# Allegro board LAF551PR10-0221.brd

Outline 338.42 x 187.55 mm; copper layers: TOP, GND1, IN1, GND2, IN2, GND3, IN3, IN4, GND4, IN5, GND5, IN6, GND6, BOTTOM. Coordinates in mm from the lower left corner of the outline.

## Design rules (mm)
net group CHR_USB20_1: nets CHR_USB20_N1 CHR_USB20_P1
net group CHR_USB20_1_R: nets CHR_USB20_N1_R CHR_USB20_P1_R
net group CSO_1: nets CSON_1 CSOP_1
net group CSS_2: nets CSSN_2 CSSP_2
net group CSS_B+: nets CSSN_B+ CSSP_B+
net group CSSUM: nets CSNSUM CSPSUM
net group DDR-ALERT: nets DDR_A_ALERT# DDR_B_ALERT#
net group DIFFPAIR70: nets CSSN_1 CSSP_1
net group DIFFPAIR85: nets TP_CLK TP_DATA
net group DIFFPAIR176: nets VGA_SMB_CK2 VGA_SMB_DA2
net group DIFFPAIR180: nets TBTA_LSRX TBTA_LSTX
net group DIFFPAIR181: nets XTALIN XTALOUT
net group DIFFPAIR194: nets RTD3_CIO_PWR_EN RTD3_USB_PWR_EN
net group DIFFPAIR195: nets I2C_0_SCL_R I2C_0_SDA_R
net group DIFFPAIR196: nets I2C_0_SCL I2C_0_SDA
net group DIFFPAIR197: nets UART_2_PRXD_DTXD UART_2_PTXD_DRXD
net group DIFFPAIR199: nets USART_RX USART_TX
net group DIFFPAIR200: nets TP_CLK_R TP_DATA_R
net group DIFFPAIR201: nets TBT_A_SBU1 TBT_A_SBU2
net group I2C0__EC: nets I2C0_SCL_EC I2C0_SDA_EC
net group I2CC_: nets I2CC_SCL I2CC_SDA
net group I2CC__R: nets I2CC_SCL_R I2CC_SDA_R
net group NVVDD_ISUM1: nets NVVDD_ISUMN1 NVVDD_ISUMP1
net group NVVDD_ISUM2: nets NVVDD_ISUMN2 NVVDD_ISUMP2
net group NVVDD_ISUM3: nets NVVDD_ISUMN3 NVVDD_ISUMP3
net group NVVDD_ISUM4: nets NVVDD_ISUMN4 NVVDD_ISUMP4
net group PCIE_RCOMP: nets PCIE_RCOMPN PCIE_RCOMPP
net group RJ45_MDI0: nets RJ45_MDIN0 RJ45_MDIP0
net group RJ45_MDI1: nets RJ45_MDIN1 RJ45_MDIP1
net group RJ45_MDI2: nets RJ45_MDIN2 RJ45_MDIP2
net group RJ45_MDI3: nets RJ45_MDIN3 RJ45_MDIP3
net group SATA_PRX_C_DTX_0: nets SATA_PRX_C_DTX_N0 SATA_PRX_C_DTX_P0
net group SATA_PRX_DTX_0: nets SATA_PRX_DTX_N0 SATA_PRX_DTX_P0
net group SATA_PTX_C_DRX_0: nets SATA_PTX_C_DRX_N0 SATA_PTX_C_DRX_P0
net group SATA_PTX_DRX_0: nets SATA_PTX_DRX_N0 SATA_PTX_DRX_P0
net group SPK_L_CONN: nets SPK_L+_CONN SPK_L-_CONN
net group SPK_R_CONN: nets SPK_R+_CONN SPK_R-_CONN
net group VIN1: nets VIN1N VIN1P
net group VIN2: nets VIN2N VIN2P
net group VIN3: nets VIN3N VIN3P
net group 12: nets DGPU_PEX_RST#
net group 15: nets TBT_EE_CLK
net group 20: nets PCH_RTCRST#
net group ASYNCHRONOUS: nets CALDERA_RST# CDRA_RST# CFG0 CFG1 CFG2 CFG3 CFG4 CFG5 CFG6 CFG7 CFG8 CFG9 CFG10 CFG11 CFG12 CFG13 CFG14 CFG15 CFG16 CFG17 CFG18 CFG19 CFG_RCOMP CPU_TRIGGER DDR_DRAMRST# DGPU_HOLD_RST# DGPU_PEX_RST#_R DGPU_PWROK EDP_RCOMP GPU_PEX_RST_HOLD# H_CPUPWRGD H_DRAMRST# H_PECI H_PM_DOWN H_PM_SYNC_R H_PROCHOT# H_THERMTRIP# H_THERMTRIP#_R H_VCCST_PWRGD IMVP_VR_ON PCH_DPWROK PCH_JTAG_TCK PCH_PECI PCH_PLTRST# PCH_PWR_EN PCH_PWROK PCH_TRIGGER PECI_KB9012 PEG_RCOMP PLTRST_CPU# SLP_S3 SLP_S5 SUSACK# SUSP# SYS_PEX_RST_MON# SYS_PWROK SYS_RESET# SYSON TBT_RST#_R USB_OC0# USB_OC2# VCCIO_PGOOD VR_SVID_ALERT# VR_SVID_CLK VR_SVID_DATA XDP_PRDY# XDP_PREQ#
net group CODEC: nets HP2_D_L_C HP2_D_L_R HP2_D_R_C HP2_D_R_R HPOUT-L HPOUT-R
net group CRITICAL LOW SPEED: nets INTRUDER# PBTN_OUT# PCH_SRTCRST# PCIE_WAKE# WAKE#
net group CRYSTAL: nets PCH_RTCX1 PCH_RTCX2 TBT_XTAL_25_IN TBT_XTAL_25_OUT XTAL24_IN XTAL24_OUT XTLI XTLO
net group DDR-RCOMP: nets DDR_RCOMP0 DDR_RCOMP1 DDR_RCOMP2
net group DDRA-CMD: nets DDR_A_BA0 DDR_A_BA1 DDR_A_BG0 DDR_A_BG1 DDR_A_MA0 DDR_A_MA1 DDR_A_MA2 DDR_A_MA3 DDR_A_MA4 DDR_A_MA5 DDR_A_MA6 DDR_A_MA7 DDR_A_MA8 DDR_A_MA9 DDR_A_MA10 DDR_A_MA11 DDR_A_MA12 DDR_A_MA13 DDR_A_MA14_WE# DDR_A_MA15_CAS# DDR_A_MA16_RAS#
net group DDRA-CTL: nets DDR_A_ACT# DDR_A_CKE0 DDR_A_CKE1 DDR_A_CS#0 DDR_A_CS#1 DDR_A_ODT0 DDR_A_ODT1 DDR_A_PAR
net group DDRA-D0: nets DDR_A_D0 DDR_A_D1 DDR_A_D2 DDR_A_D3 DDR_A_D4 DDR_A_D5 DDR_A_D6 DDR_A_D7
net group DDRA-D1: nets DDR_A_D8 DDR_A_D9 DDR_A_D10 DDR_A_D11 DDR_A_D12 DDR_A_D13 DDR_A_D14 DDR_A_D15
net group DDRA-D2: nets DDR_A_D16 DDR_A_D17 DDR_A_D18 DDR_A_D19 DDR_A_D20 DDR_A_D21 DDR_A_D22 DDR_A_D23
net group DDRA-D3: nets DDR_A_D24 DDR_A_D25 DDR_A_D26 DDR_A_D27 DDR_A_D28 DDR_A_D29 DDR_A_D30 DDR_A_D31
net group DDRA-D4: nets DDR_A_D32 DDR_A_D33 DDR_A_D34 DDR_A_D35 DDR_A_D36 DDR_A_D37 DDR_A_D38 DDR_A_D39
net group DDRA-D5: nets DDR_A_D40 DDR_A_D41 DDR_A_D42 DDR_A_D43 DDR_A_D44 DDR_A_D45 DDR_A_D46 DDR_A_D47
net group DDRA-D6: nets DDR_A_D48 DDR_A_D49 DDR_A_D50 DDR_A_D51 DDR_A_D52 DDR_A_D53 DDR_A_D54 DDR_A_D55
net group DDRA-D7: nets DDR_A_D56 DDR_A_D57 DDR_A_D58 DDR_A_D59 DDR_A_D60 DDR_A_D61 DDR_A_D62 DDR_A_D63
net group DDRA-DQS: nets DDR_A_DQS0 DDR_A_DQS1 DDR_A_DQS2 DDR_A_DQS3 DDR_A_DQS4 DDR_A_DQS5 DDR_A_DQS6 DDR_A_DQS7 DDR_A_DQS#0 DDR_A_DQS#1 DDR_A_DQS#2 DDR_A_DQS#3 DDR_A_DQS#4 DDR_A_DQS#5 DDR_A_DQS#6 DDR_A_DQS#7
net group DDRB-CMD: nets DDR_B_BA0 DDR_B_BA1 DDR_B_BG0 DDR_B_BG1 DDR_B_MA0 DDR_B_MA1 DDR_B_MA2 DDR_B_MA3 DDR_B_MA4 DDR_B_MA5 DDR_B_MA6 DDR_B_MA7 DDR_B_MA8 DDR_B_MA9 DDR_B_MA10 DDR_B_MA11 DDR_B_MA12 DDR_B_MA13 DDR_B_MA14_WE# DDR_B_MA15_CAS# DDR_B_MA16_RAS#
net group DDRB-CTL: nets DDR_B_ACT# DDR_B_CKE0 DDR_B_CKE1 DDR_B_CS#0 DDR_B_CS#1 DDR_B_ODT0 DDR_B_ODT1 DDR_B_PAR
net group DDRB-D0: nets DDR_B_D0 DDR_B_D1 DDR_B_D2 DDR_B_D3 DDR_B_D4 DDR_B_D5 DDR_B_D6 DDR_B_D7
net group DDRB-D1: nets DDR_B_D8 DDR_B_D9 DDR_B_D10 DDR_B_D11 DDR_B_D12 DDR_B_D13 DDR_B_D14 DDR_B_D15
net group DDRB-D2: nets DDR_B_D16 DDR_B_D17 DDR_B_D18 DDR_B_D19 DDR_B_D20 DDR_B_D21 DDR_B_D22 DDR_B_D23
net group DDRB-D3: nets DDR_B_D24 DDR_B_D25 DDR_B_D26 DDR_B_D27 DDR_B_D28 DDR_B_D29 DDR_B_D30 DDR_B_D31
net group DDRB-D4: nets DDR_B_D32 DDR_B_D33 DDR_B_D34 DDR_B_D35 DDR_B_D36 DDR_B_D37 DDR_B_D38 DDR_B_D39
net group DDRB-D5: nets DDR_B_D40 DDR_B_D41 DDR_B_D42 DDR_B_D43 DDR_B_D44 DDR_B_D45 DDR_B_D46 DDR_B_D47
net group DDRB-D6: nets DDR_B_D48 DDR_B_D49 DDR_B_D50 DDR_B_D51 DDR_B_D52 DDR_B_D53 DDR_B_D54 DDR_B_D55
net group DDRB-D7: nets DDR_B_D56 DDR_B_D57 DDR_B_D58 DDR_B_D59 DDR_B_D60 DDR_B_D61 DDR_B_D62 DDR_B_D63
net group DDRB-DQS: nets DDR_B_DQS0 DDR_B_DQS1 DDR_B_DQS2 DDR_B_DQS3 DDR_B_DQS4 DDR_B_DQS5 DDR_B_DQS6 DDR_B_DQS7 DDR_B_DQS#0 DDR_B_DQS#1 DDR_B_DQS#2 DDR_B_DQS#3 DDR_B_DQS#4 DDR_B_DQS#5 DDR_B_DQS#6 DDR_B_DQS#7
net group DDRCLK: nets DDR_A_CLK0 DDR_A_CLK1 DDR_A_CLK#0 DDR_A_CLK#1 DDR_B_CLK0 DDR_B_CLK1 DDR_B_CLK#0 DDR_B_CLK#1
net group DIFFPAIR148: nets REMOTE3-
net group DMI: nets DMI_CRX_PTX_N0 DMI_CRX_PTX_N1 DMI_CRX_PTX_N2 DMI_CRX_PTX_N3 DMI_CRX_PTX_P0 DMI_CRX_PTX_P1 DMI_CRX_PTX_P2 DMI_CRX_PTX_P3 DMI_CTX_PRX_N0 DMI_CTX_PRX_N1 DMI_CTX_PRX_N2 DMI_CTX_PRX_N3 DMI_CTX_PRX_P0 DMI_CTX_PRX_P1 DMI_CTX_PRX_P2 DMI_CTX_PRX_P3 DMIC_CLK1_R DMIC_DATA1_R
net group DP: nets CPU_DDC1CLK CPU_DDC1CLK_R CPU_DDC1DATA CPU_DDC1DATA_R CPU_DDC2CLK CPU_DDC2CLK_R CPU_DDC2DATA CPU_DDC2DATA_R CPU_DP1_AUXN CPU_DP1_AUXN_C CPU_DP1_AUXP CPU_DP1_AUXP_C CPU_DP1_N0 CPU_DP1_N0_C CPU_DP1_N1 CPU_DP1_N1_C CPU_DP1_N2 CPU_DP1_N2_C CPU_DP1_N3 CPU_DP1_N3_C CPU_DP1_P0 CPU_DP1_P0_C CPU_DP1_P1 CPU_DP1_P1_C CPU_DP1_P2 CPU_DP1_P2_C CPU_DP1_P3 CPU_DP1_P3_C CPU_DP2_AUXN CPU_DP2_AUXN_C CPU_DP2_AUXP CPU_DP2_AUXP_C CPU_DP2_N0 CPU_DP2_N0_C CPU_DP2_N1 CPU_DP2_N1_C CPU_DP2_N2 CPU_DP2_N2_C CPU_DP2_N3 CPU_DP2_N3_C CPU_DP2_P0 CPU_DP2_P0_C CPU_DP2_P1 CPU_DP2_P1_C CPU_DP2_P2 CPU_DP2_P2_C CPU_DP2_P3 CPU_DP2_P3_C GPU_DP_AUXN GPU_DP_AUXN_C GPU_DP_AUXN_R GPU_DP_AUXP GPU_DP_AUXP_C GPU_DP_AUXP_R GPU_DP_N0 GPU_DP_N0_C GPU_DP_N1 GPU_DP_N1_C GPU_DP_N2 GPU_DP_N2_C GPU_DP_N3 GPU_DP_N3_C GPU_DP_P0 GPU_DP_P0_C GPU_DP_P1 GPU_DP_P1_C GPU_DP_P2 GPU_DP_P2_C GPU_DP_P3 GPU_DP_P3_C
net group EDP-MUX: nets EDP_AUXN EDP_AUXN_C EDP_AUXP EDP_AUXP_C EDP_TXN0 EDP_TXN0_C EDP_TXN1 EDP_TXN1_C EDP_TXN2 EDP_TXN2_C EDP_TXN3 EDP_TXN3_C EDP_TXP0 EDP_TXP0_C EDP_TXP1 EDP_TXP1_C EDP_TXP2 EDP_TXP2_C EDP_TXP3 EDP_TXP3_C
net group EMC: nets BOOT_1.2V BST_1.2V BST_3V BST_5V CPU_XDP_TRST# MIC_CLK MIC_DATA RJ45_CT0 RJ45_CT1 RJ45_CT2 RJ45_CT3 TBT_TCK
net group FB_A_WCK01: nets FB_A_WCK#01
net group FB_A_WCK23: nets FB_A_WCK#23
net group FB_A_WCK45: nets FB_A_WCK#45
net group FB_A_WCK67: nets FB_A_WCK#67
net group FBA-CLK: nets FB_A_CLK0 FB_A_CLK1 FB_A_CLK#0 FB_A_CLK#1
net group FBA-CMD: nets FB_A_CMD0 FB_A_CMD1 FB_A_CMD2 FB_A_CMD3 FB_A_CMD4 FB_A_CMD5 FB_A_CMD6 FB_A_CMD7 FB_A_CMD8 FB_A_CMD9 FB_A_CMD10 FB_A_CMD11 FB_A_CMD12 FB_A_CMD13 FB_A_CMD14 FB_A_CMD15 FB_A_CMD16 FB_A_CMD17 FB_A_CMD18 FB_A_CMD19 FB_A_CMD20 FB_A_CMD21 FB_A_CMD22 FB_A_CMD23 FB_A_CMD24 FB_A_CMD25 FB_A_CMD26 FB_A_CMD27 FB_A_CMD28 FB_A_CMD29 FB_A_CMD30 FB_A_CMD31
net group FBA-D0: nets FB_A_D0 FB_A_D1 FB_A_D2 FB_A_D3 FB_A_D4 FB_A_D5 FB_A_D6 FB_A_D7
net group FBA-D1: nets FB_A_D8 FB_A_D9 FB_A_D10 FB_A_D11 FB_A_D12 FB_A_D13 FB_A_D14 FB_A_D15
net group FBA-D2: nets FB_A_D16 FB_A_D17 FB_A_D18 FB_A_D19 FB_A_D20 FB_A_D21 FB_A_D22 FB_A_D23
net group FBA-D3: nets FB_A_D24 FB_A_D25 FB_A_D26 FB_A_D27 FB_A_D28 FB_A_D29 FB_A_D30 FB_A_D31
net group FBA-D4: nets FB_A_D32 FB_A_D33 FB_A_D34 FB_A_D35 FB_A_D36 FB_A_D37 FB_A_D38 FB_A_D39
net group FBA-D5: nets FB_A_D40 FB_A_D41 FB_A_D42 FB_A_D43 FB_A_D44 FB_A_D45 FB_A_D46 FB_A_D47
net group FBA-D6: nets FB_A_D48 FB_A_D49 FB_A_D50 FB_A_D51 FB_A_D52 FB_A_D53 FB_A_D54 FB_A_D55
net group FBA-D7: nets FB_A_D56 FB_A_D57 FB_A_D58 FB_A_D59 FB_A_D60 FB_A_D61 FB_A_D62 FB_A_D63
net group FBA-DBI: nets FB_A_DBI0 FB_A_DBI1 FB_A_DBI2 FB_A_DBI3 FB_A_DBI4 FB_A_DBI5 FB_A_DBI6 FB_A_DBI7
net group FBA-EDC: nets FB_A_EDC0 FB_A_EDC1 FB_A_EDC2 FB_A_EDC3 FB_A_EDC4 FB_A_EDC5 FB_A_EDC6 FB_A_EDC7
net group FBA-WCK: nets FB_A_WCK01 FB_A_WCK23 FB_A_WCK45 FB_A_WCK67
net group FBB-CLK: nets FB_B_CLK0 FB_B_CLK1 FB_B_CLK#0 FB_B_CLK#1
net group FBB-CMD: nets FB_B_CMD0 FB_B_CMD1 FB_B_CMD2 FB_B_CMD3 FB_B_CMD4 FB_B_CMD5 FB_B_CMD6 FB_B_CMD7 FB_B_CMD8 FB_B_CMD9 FB_B_CMD10 FB_B_CMD11 FB_B_CMD12 FB_B_CMD13 FB_B_CMD14 FB_B_CMD15 FB_B_CMD16 FB_B_CMD17 FB_B_CMD18 FB_B_CMD19 FB_B_CMD20 FB_B_CMD21 FB_B_CMD22 FB_B_CMD23 FB_B_CMD24 FB_B_CMD25 FB_B_CMD26 FB_B_CMD27 FB_B_CMD28 FB_B_CMD29 FB_B_CMD30 FB_B_CMD31
net group FBB-D0: nets FB_B_D0 FB_B_D1 FB_B_D2 FB_B_D3 FB_B_D4 FB_B_D5 FB_B_D6 FB_B_D7
net group FBB-D1: nets FB_B_D8 FB_B_D9 FB_B_D10 FB_B_D11 FB_B_D12 FB_B_D13 FB_B_D14 FB_B_D15
net group FBB-D2: nets FB_B_D16 FB_B_D17 FB_B_D18 FB_B_D19 FB_B_D20 FB_B_D21 FB_B_D22 FB_B_D23
net group FBB-D3: nets FB_B_D24 FB_B_D25 FB_B_D26 FB_B_D27 FB_B_D28 FB_B_D29 FB_B_D30 FB_B_D31
net group FBB-D4: nets FB_B_D32 FB_B_D33 FB_B_D34 FB_B_D35 FB_B_D36 FB_B_D37 FB_B_D38 FB_B_D39
net group FBB-D5: nets FB_B_D40 FB_B_D41 FB_B_D42 FB_B_D43 FB_B_D44 FB_B_D45 FB_B_D46 FB_B_D47
net group FBB-D6: nets FB_B_D48 FB_B_D49 FB_B_D50 FB_B_D51 FB_B_D52 FB_B_D53 FB_B_D54 FB_B_D55
net group FBB-D7: nets FB_B_D56 FB_B_D57 FB_B_D58 FB_B_D59 FB_B_D60 FB_B_D61 FB_B_D62 FB_B_D63
net group FBB-DBI: nets FB_B_DBI0 FB_B_DBI1 FB_B_DBI2 FB_B_DBI3 FB_B_DBI4 FB_B_DBI5 FB_B_DBI6 FB_B_DBI7
net group FBB-EDC: nets FB_B_EDC0 FB_B_EDC1 FB_B_EDC2 FB_B_EDC3 FB_B_EDC4 FB_B_EDC5 FB_B_EDC6 FB_B_EDC7
net group FBB-WCK: nets FB_B_WCK01 FB_B_WCK23 FB_B_WCK45 FB_B_WCK67 FB_B_WCK#01 FB_B_WCK#23 FB_B_WCK#45 FB_B_WCK#67
net group FBC-CLK: nets FB_C_CLK0 FB_C_CLK1 FB_C_CLK#0 FB_C_CLK#1
net group FBC-CMD: nets FB_C_CMD0 FB_C_CMD1 FB_C_CMD2 FB_C_CMD3 FB_C_CMD4 FB_C_CMD5 FB_C_CMD6 FB_C_CMD7 FB_C_CMD8 FB_C_CMD9 FB_C_CMD10 FB_C_CMD11 FB_C_CMD12 FB_C_CMD13 FB_C_CMD14 FB_C_CMD15 FB_C_CMD16 FB_C_CMD17 FB_C_CMD18 FB_C_CMD19 FB_C_CMD20 FB_C_CMD21 FB_C_CMD22 FB_C_CMD23 FB_C_CMD24 FB_C_CMD25 FB_C_CMD26 FB_C_CMD27 FB_C_CMD28 FB_C_CMD29 FB_C_CMD30 FB_C_CMD31
net group FBC-D0: nets FB_C_D0 FB_C_D1 FB_C_D2 FB_C_D3 FB_C_D4 FB_C_D5 FB_C_D6 FB_C_D7
net group FBC-D1: nets FB_C_D8 FB_C_D9 FB_C_D10 FB_C_D11 FB_C_D12 FB_C_D13 FB_C_D14 FB_C_D15
net group FBC-D2: nets FB_C_D16 FB_C_D17 FB_C_D18 FB_C_D19 FB_C_D20 FB_C_D21 FB_C_D22 FB_C_D23
net group FBC-D3: nets FB_C_D24 FB_C_D25 FB_C_D26 FB_C_D27 FB_C_D28 FB_C_D29 FB_C_D30 FB_C_D31
net group FBC-D4: nets FB_C_D32 FB_C_D33 FB_C_D34 FB_C_D35 FB_C_D36 FB_C_D37 FB_C_D38 FB_C_D39
net group FBC-D5: nets FB_C_D40 FB_C_D41 FB_C_D42 FB_C_D43 FB_C_D44 FB_C_D45 FB_C_D46 FB_C_D47
net group FBC-D6: nets FB_C_D48 FB_C_D49 FB_C_D50 FB_C_D51 FB_C_D52 FB_C_D53 FB_C_D54 FB_C_D55
net group FBC-D7: nets FB_C_D56 FB_C_D57 FB_C_D58 FB_C_D59 FB_C_D60 FB_C_D61 FB_C_D62 FB_C_D63
net group FBC-DBI: nets FB_C_DBI0 FB_C_DBI1 FB_C_DBI2 FB_C_DBI3 FB_C_DBI4 FB_C_DBI5 FB_C_DBI6 FB_C_DBI7
net group FBC-EDC: nets FB_C_EDC0 FB_C_EDC1 FB_C_EDC2 FB_C_EDC3 FB_C_EDC4 FB_C_EDC5 FB_C_EDC6 FB_C_EDC7
net group FBC-WCK: nets FB_C_WCK01 FB_C_WCK23 FB_C_WCK45 FB_C_WCK67 FB_C_WCK#01 FB_C_WCK#23 FB_C_WCK#45 FB_C_WCK#67
net group FBD-CLK: nets FB_D_CLK0 FB_D_CLK1 FB_D_CLK#0 FB_D_CLK#1
net group FBD-CMD: nets FB_D_CMD0 FB_D_CMD1 FB_D_CMD2 FB_D_CMD3 FB_D_CMD4 FB_D_CMD5 FB_D_CMD6 FB_D_CMD7 FB_D_CMD8 FB_D_CMD9 FB_D_CMD10 FB_D_CMD11 FB_D_CMD12 FB_D_CMD13 FB_D_CMD14 FB_D_CMD15 FB_D_CMD16 FB_D_CMD17 FB_D_CMD18 FB_D_CMD19 FB_D_CMD20 FB_D_CMD21 FB_D_CMD22 FB_D_CMD23 FB_D_CMD24 FB_D_CMD25 FB_D_CMD26 FB_D_CMD27 FB_D_CMD28 FB_D_CMD29 FB_D_CMD30 FB_D_CMD31
net group FBD-D0: nets FB_D_D0 FB_D_D1 FB_D_D2 FB_D_D3 FB_D_D4 FB_D_D5 FB_D_D6 FB_D_D7
net group FBD-D1: nets FB_D_D8 FB_D_D9 FB_D_D10 FB_D_D11 FB_D_D12 FB_D_D13 FB_D_D14 FB_D_D15
net group FBD-D2: nets FB_D_D16 FB_D_D17 FB_D_D18 FB_D_D19 FB_D_D20 FB_D_D21 FB_D_D22 FB_D_D23
net group FBD-D3: nets FB_D_D24 FB_D_D25 FB_D_D26 FB_D_D27 FB_D_D28 FB_D_D29 FB_D_D30 FB_D_D31
net group FBD-D4: nets FB_D_D32 FB_D_D33 FB_D_D34 FB_D_D35 FB_D_D36 FB_D_D37 FB_D_D38 FB_D_D39
net group FBD-D5: nets FB_D_D40 FB_D_D41 FB_D_D42 FB_D_D43 FB_D_D44 FB_D_D45 FB_D_D46 FB_D_D47
net group FBD-D6: nets FB_D_D48 FB_D_D49 FB_D_D50 FB_D_D51 FB_D_D52 FB_D_D53 FB_D_D54 FB_D_D55
net group FBD-D7: nets FB_D_D56 FB_D_D57 FB_D_D58 FB_D_D59 FB_D_D60 FB_D_D61 FB_D_D62 FB_D_D63
net group FBD-DBI: nets FB_D_DBI0 FB_D_DBI1 FB_D_DBI2 FB_D_DBI3 FB_D_DBI4 FB_D_DBI5 FB_D_DBI6 FB_D_DBI7
net group FBD-EDC: nets FB_D_EDC0 FB_D_EDC1 FB_D_EDC2 FB_D_EDC3 FB_D_EDC4 FB_D_EDC5 FB_D_EDC6 FB_D_EDC7
net group FBD-WCK: nets FB_D_WCK01 FB_D_WCK23 FB_D_WCK45 FB_D_WCK67 FB_D_WCK#01 FB_D_WCK#23 FB_D_WCK#45 FB_D_WCK#67
net group HDA: nets HDA_BIT_CLK HDA_BIT_CLK_R HDA_RST# HDA_RST#_R HDA_SDIN HDA_SDIN_R HDA_SDOUT HDA_SDOUT_R HDA_SPKR HDA_SYNC HDA_SYNC_R ME_EN
net group HDMI: nets GPU_HDMI_CLKN GPU_HDMI_CLKP GPU_HDMI_TX_N0 GPU_HDMI_TX_N1 GPU_HDMI_TX_N2 GPU_HDMI_TX_P0 GPU_HDMI_TX_P1 GPU_HDMI_TX_P2 HDMI_C_CLKN HDMI_C_CLKP HDMI_C_TX_N0 HDMI_C_TX_N1 HDMI_C_TX_N2 HDMI_C_TX_P0 HDMI_C_TX_P1 HDMI_C_TX_P2 HDMI_CLKN HDMI_CLKP HDMI_L_CLKN HDMI_L_CLKP HDMI_L_TX_N0 HDMI_L_TX_N1 HDMI_L_TX_N2 HDMI_L_TX_P0 HDMI_L_TX_P1 HDMI_L_TX_P2 HDMI_TX_N0 HDMI_TX_N1 HDMI_TX_N2 HDMI_TX_P0 HDMI_TX_P1 HDMI_TX_P2
net group I2C: nets CDRA_CLK CDRA_DAT I2C_CLK I2C_DAT I2C_INT TBT_I2C_SCL TBT_I2C_SDA TBTA_I2C_INT TBTA_I2C_SCL1_R TBTA_I2C_SDA1_R TBTB_I2C_INT
net group LAN: nets LAN_MDIN0 LAN_MDIN1 LAN_MDIN2 LAN_MDIN3 LAN_MDIP0 LAN_MDIP1 LAN_MDIP2 LAN_MDIP3
net group LPC: nets LPC_AD0 LPC_AD1 LPC_AD2 LPC_AD3 LPC_FRAME#
net group MDP: nets DISP_CLK_AUXP_CONN
net group PCIE: nets PCIE_PRX_C_DTX_N15 PCIE_PRX_C_DTX_P15 PCIE_PRX_DTX_N9 PCIE_PRX_DTX_N10 PCIE_PRX_DTX_N11 PCIE_PRX_DTX_N12 PCIE_PRX_DTX_N15 PCIE_PRX_DTX_N16 PCIE_PRX_DTX_N17 PCIE_PRX_DTX_N18 PCIE_PRX_DTX_N19 PCIE_PRX_DTX_N20 PCIE_PRX_DTX_N21 PCIE_PRX_DTX_N22 PCIE_PRX_DTX_N23 PCIE_PRX_DTX_N24 PCIE_PRX_DTX_P9 PCIE_PRX_DTX_P10 PCIE_PRX_DTX_P11 PCIE_PRX_DTX_P12 PCIE_PRX_DTX_P15 PCIE_PRX_DTX_P16 PCIE_PRX_DTX_P17 PCIE_PRX_DTX_P18 PCIE_PRX_DTX_P19 PCIE_PRX_DTX_P20 PCIE_PRX_DTX_P21 PCIE_PRX_DTX_P22 PCIE_PRX_DTX_P23 PCIE_PRX_DTX_P24 PCIE_PTX_C_DRX_N9 PCIE_PTX_C_DRX_N10 PCIE_PTX_C_DRX_N11 PCIE_PTX_C_DRX_N12 PCIE_PTX_C_DRX_N15 PCIE_PTX_C_DRX_N16 PCIE_PTX_C_DRX_N17 PCIE_PTX_C_DRX_N18 PCIE_PTX_C_DRX_N19 PCIE_PTX_C_DRX_N20 PCIE_PTX_C_DRX_N21 PCIE_PTX_C_DRX_N22 PCIE_PTX_C_DRX_N23 PCIE_PTX_C_DRX_N24 PCIE_PTX_C_DRX_P9 PCIE_PTX_C_DRX_P10 PCIE_PTX_C_DRX_P11 PCIE_PTX_C_DRX_P12 PCIE_PTX_C_DRX_P15 PCIE_PTX_C_DRX_P16 PCIE_PTX_C_DRX_P17 PCIE_PTX_C_DRX_P18 PCIE_PTX_C_DRX_P19 PCIE_PTX_C_DRX_P20 PCIE_PTX_C_DRX_P21 PCIE_PTX_C_DRX_P22 PCIE_PTX_C_DRX_P23 PCIE_PTX_C_DRX_P24 PCIE_PTX_DRX_N9 PCIE_PTX_DRX_N10 PCIE_PTX_DRX_N11 PCIE_PTX_DRX_N12 PCIE_PTX_DRX_N15 PCIE_PTX_DRX_N16 PCIE_PTX_DRX_N17 PCIE_PTX_DRX_N18 PCIE_PTX_DRX_N19 PCIE_PTX_DRX_N20 PCIE_PTX_DRX_N21 PCIE_PTX_DRX_N22 PCIE_PTX_DRX_N23 PCIE_PTX_DRX_N24 PCIE_PTX_DRX_P9 PCIE_PTX_DRX_P10 PCIE_PTX_DRX_P11 PCIE_PTX_DRX_P12 PCIE_PTX_DRX_P15 PCIE_PTX_DRX_P16 PCIE_PTX_DRX_P17 PCIE_PTX_DRX_P18 PCIE_PTX_DRX_P19 PCIE_PTX_DRX_P20 PCIE_PTX_DRX_P21 PCIE_PTX_DRX_P22 PCIE_PTX_DRX_P23 PCIE_PTX_DRX_P24
net group PEG: nets PEG_CRX_C_GTX_N0 PEG_CRX_C_GTX_N1 PEG_CRX_C_GTX_N2 PEG_CRX_C_GTX_N3 PEG_CRX_C_GTX_N4 PEG_CRX_C_GTX_N5 PEG_CRX_C_GTX_N6 PEG_CRX_C_GTX_N7 PEG_CRX_C_GTX_P0 PEG_CRX_C_GTX_P1 PEG_CRX_C_GTX_P2 PEG_CRX_C_GTX_P3 PEG_CRX_C_GTX_P4 PEG_CRX_C_GTX_P5 PEG_CRX_C_GTX_P6 PEG_CRX_C_GTX_P7 PEG_CRX_C_RD_GTX_N8 PEG_CRX_C_RD_GTX_N9 PEG_CRX_C_RD_GTX_N10 PEG_CRX_C_RD_GTX_N11 PEG_CRX_C_RD_GTX_P8 PEG_CRX_C_RD_GTX_P9 PEG_CRX_C_RD_GTX_P10 PEG_CRX_C_RD_GTX_P11 PEG_CRX_C_TTX_N12 PEG_CRX_C_TTX_N13 PEG_CRX_C_TTX_N14 PEG_CRX_C_TTX_N15 PEG_CRX_C_TTX_P12 PEG_CRX_C_TTX_P13 PEG_CRX_C_TTX_P14 PEG_CRX_C_TTX_P15 PEG_CRX_GTX_N0 PEG_CRX_GTX_N1 PEG_CRX_GTX_N2 PEG_CRX_GTX_N3 PEG_CRX_GTX_N4 PEG_CRX_GTX_N5 PEG_CRX_GTX_N6 PEG_CRX_GTX_N7 PEG_CRX_GTX_N8 PEG_CRX_GTX_N9 PEG_CRX_GTX_N10 PEG_CRX_GTX_N11 PEG_CRX_GTX_P0 PEG_CRX_GTX_P1 PEG_CRX_GTX_P2 PEG_CRX_GTX_P3 PEG_CRX_GTX_P4 PEG_CRX_GTX_P5 PEG_CRX_GTX_P6 PEG_CRX_GTX_P7 PEG_CRX_GTX_P8 PEG_CRX_GTX_P9 PEG_CRX_GTX_P10 PEG_CRX_GTX_P11 PEG_CRX_RD_GTX_N8 PEG_CRX_RD_GTX_N9 PEG_CRX_RD_GTX_N10 PEG_CRX_RD_GTX_N11 PEG_CRX_RD_GTX_P8 PEG_CRX_RD_GTX_P9 PEG_CRX_RD_GTX_P10 PEG_CRX_RD_GTX_P11 PEG_CRX_TTX_N12 PEG_CRX_TTX_N13 PEG_CRX_TTX_N14 PEG_CRX_TTX_N15 PEG_CRX_TTX_P12 PEG_CRX_TTX_P13 PEG_CRX_TTX_P14 PEG_CRX_TTX_P15 PEG_CTX_C_GRX_N0 PEG_CTX_C_GRX_N1 PEG_CTX_C_GRX_N2 PEG_CTX_C_GRX_N3 PEG_CTX_C_GRX_N4 PEG_CTX_C_GRX_N5 PEG_CTX_C_GRX_N6 PEG_CTX_C_GRX_N7 PEG_CTX_C_GRX_N8 PEG_CTX_C_GRX_N9 PEG_CTX_C_GRX_N10 PEG_CTX_C_GRX_N11 PEG_CTX_C_GRX_P0 PEG_CTX_C_GRX_P1 PEG_CTX_C_GRX_P2 PEG_CTX_C_GRX_P3 PEG_CTX_C_GRX_P4 PEG_CTX_C_GRX_P5 PEG_CTX_C_GRX_P6 PEG_CTX_C_GRX_P7 PEG_CTX_C_GRX_P8 PEG_CTX_C_GRX_P9 PEG_CTX_C_GRX_P10 PEG_CTX_C_GRX_P11 PEG_CTX_C_TRX_N12 PEG_CTX_C_TRX_N13 PEG_CTX_C_TRX_N14 PEG_CTX_C_TRX_N15 PEG_CTX_C_TRX_P12 PEG_CTX_C_TRX_P13 PEG_CTX_C_TRX_P14 PEG_CTX_C_TRX_P15 PEG_CTX_GRX_N0 PEG_CTX_GRX_N1 PEG_CTX_GRX_N2 PEG_CTX_GRX_N3 PEG_CTX_GRX_N4 PEG_CTX_GRX_N5 PEG_CTX_GRX_N6 PEG_CTX_GRX_N7 PEG_CTX_GRX_N8 PEG_CTX_GRX_N9 PEG_CTX_GRX_N10 PEG_CTX_GRX_N11 PEG_CTX_GRX_P0 PEG_CTX_GRX_P1 PEG_CTX_GRX_P2 PEG_CTX_GRX_P3 PEG_CTX_GRX_P4 PEG_CTX_GRX_P5 PEG_CTX_GRX_P6 PEG_CTX_GRX_P7 PEG_CTX_GRX_P8 PEG_CTX_GRX_P9 PEG_CTX_GRX_P10 PEG_CTX_GRX_P11 PEG_CTX_TRX_N12 PEG_CTX_TRX_N13 PEG_CTX_TRX_N14 PEG_CTX_TRX_N15 PEG_CTX_TRX_P12 PEG_CTX_TRX_P13 PEG_CTX_TRX_P14 PEG_CTX_TRX_P15
net group PLATFORM-CLK: nets CLK_PCI_LPC CLK_PCIE_DGPU#_C CLK_PCIE_DGPU_C CLK_PCIE_N1 CLK_PCIE_N2 CLK_PCIE_N3 CLK_PCIE_N4 CLK_PCIE_N5 CLK_PCIE_N7 CLK_PCIE_P1 CLK_PCIE_P2 CLK_PCIE_P3 CLK_PCIE_P4 CLK_PCIE_P5 CLK_PCIE_P7 CLK_PEG_N0 CLK_PEG_N6 CLK_PEG_P0 CLK_PEG_P6 CPU_24MHZ_N CPU_24MHZ_P PCH_CPU_BCLK_N PCH_CPU_BCLK_P PCH_CPU_PCIBCLK_N PCH_CPU_PCIBCLK_P PCH_XDP_CLK_N PCH_XDP_CLK_P
net group POWER: nets +0.6VS +0.6VSP +0.9V_CIO +0.9V_LVR_OUT +0.9V_SVR +0.9V_USB +1.2V_VCCPLL_OC +1.2VP +1.8VA_TBTA_LDO +1.8VD_TBTA_LDO +1V_MPHY +1V_PCH +1V_VCCDSW +1VALWP +1VALWP_B+ +2.5V_MEM +2.5V_MEMP +2.5VOUT +2.5VSP_ON +2.5VSP_VIN +3.3V_1.8V_DVDD +3.3V_1.8V_DVDD_IO +3.3V_ANA_PCIE +3.3V_ANA_USB2 +3.3V_FLASH +3.3V_LC +3.3V_TBT_SX +3.3V_TBT_SX_R +3V_PCH +3VALW_PD +3VALWP +3VLP +3VS_DP +3VS_TBT +3VS_TOUCH +5V_PVDD +5V_TOBII +5V_USB_PWR1 +5V_USB_PWR2 +5V_USBC_VBUS +5VA +5VALW_LED +5VALWP +5VS_TP_LED +AVDDH +AVDDL +CODEC_AVDD2 +DVDDL +EC_VCCA +HDMI_5V_OUT +INV_PWR_SRC +LAN_IO +LCDVDD +PVDD +RBIAS +RTC_CELL +TBTA_VBUS +V18R +VCCIOP +VCCST +VCCSTG +VDD_TOUCH +VDDCT_L
net group SENSE: nets VCCGT_SENSE VCCIO_SENSE VCCSA_SENSE VCCSENSE VSSGT_SENSE VSSIO_SENSE VSSSA_SENSE VSSSENSE
net group SMBUS: nets CLK_SMB DAT_SMB EC_SMB_CK1 EC_SMB_CK2 EC_SMB_DA1 EC_SMB_DA2 PCH_SMBCLK PCH_SMBDATA SML0CLK SML0DATA SML1CLK SML1DATA
net group SPI: nets PCH_SPI_0_CLK PCH_SPI_0_CLK_R PCH_SPI_0_CS# PCH_SPI_0_HOLD# PCH_SPI_0_SI PCH_SPI_0_SO PCH_SPI_0_SO_R PCH_SPI_0_WP# PCH_SPI_0_WP#_R PCH_SYS_PWROK_XDP PD_EE_CLK PD_EE_CS_N PD_EE_DI PD_EE_DO ROM_CS# ROM_SCLK ROM_SI ROM_SO SPI_CLK SPI_CS# SPI_MOSI TBT_EE_CS_N TBT_EE_DI TBT_EE_DO TBT_EE_WP_N
net group TBT: nets TBT_A_AUX_N TBT_A_AUX_N_C TBT_A_AUX_P TBT_A_AUX_P_C TBT_A_TRX_DTX_N0 TBT_A_TRX_DTX_N1 TBT_A_TRX_DTX_P0 TBT_A_TRX_DTX_P1 TBT_A_TTX_C_DRX_N0 TBT_A_TTX_C_DRX_N1 TBT_A_TTX_C_DRX_P0 TBT_A_TTX_C_DRX_P1 TBT_A_TTX_DRX_N0 TBT_A_TTX_DRX_N1 TBT_A_TTX_DRX_P0 TBT_A_TTX_DRX_P1 TBTA_DIG_AUD_N TBTA_DIG_AUD_P
net group THERMAL: nets REMOTE1+ REMOTE1- REMOTE2+ REMOTE2- REMOTE3+
net group TMDS-MDP: nets DISP_DAT_AUXN_CONN
net group USB20: nets TBT_A_USB20_L_NB TBT_A_USB20_L_NT TBT_A_USB20_L_PB TBT_A_USB20_L_PT TBT_A_USB20_N TBT_A_USB20_NB TBT_A_USB20_NT TBT_A_USB20_P TBT_A_USB20_PB TBT_A_USB20_PT USB20_N1 USB20_N2 USB20_N3 USB20_N3_R USB20_N4 USB20_N6 USB20_N7 USB20_N7_R USB20_N8 USB20_N8_R USB20_N9 USB20_N9_R USB20_N10 USB20_N11 USB20_N11_R USB20_N14 USB20_P1 USB20_P2 USB20_P3 USB20_P3_R USB20_P4 USB20_P6 USB20_P7 USB20_P7_R USB20_P8 USB20_P8_R USB20_P9 USB20_P9_R USB20_P10 USB20_P11 USB20_P11_R USB20_P14
net group USB30: nets USB3_A_PRX_L_DTX_N2 USB3_A_PRX_L_DTX_P2 USB3_A_PRX_RD_DTX_N2 USB3_A_PRX_RD_DTX_P2 USB3_A_PTX_C_DRX_N1 USB3_A_PTX_C_DRX_P1 USB3_A_PTX_L_DRX_N1 USB3_A_PTX_L_DRX_P1 USB3_A_PTX_RD_DRX_N1 USB3_A_PTX_RD_DRX_P1 USB3_B_PRX_L_DTX_N1 USB3_B_PRX_L_DTX_P1 USB3_B_PRX_RD_DTX_N1 USB3_B_PRX_RD_DTX_P1 USB3_B_PTX_C_DRX_N2 USB3_B_PTX_C_DRX_P2 USB3_B_PTX_L_DRX_N2 USB3_B_PTX_L_DRX_P2 USB3_B_PTX_RD_DRX_N2 USB3_B_PTX_RD_DRX_P2 USB3_PRX_C_DTX_N8 USB3_PRX_C_DTX_P8 USB3_PRX_C_RD_DTX_N1 USB3_PRX_C_RD_DTX_P1 USB3_PRX_DTX_N1 USB3_PRX_DTX_N6 USB3_PRX_DTX_N7 USB3_PRX_DTX_N8 USB3_PRX_DTX_P1 USB3_PRX_DTX_P6 USB3_PRX_DTX_P7 USB3_PRX_DTX_P8 USB3_PRX_L_DTX_N6 USB3_PRX_L_DTX_P6 USB3_PTX_C_DRX_N6 USB3_PTX_C_DRX_P6 USB3_PTX_C_RD_DRX_N1 USB3_PTX_C_RD_DRX_P1 USB3_PTX_DRX_N1 USB3_PTX_DRX_N6 USB3_PTX_DRX_N7 USB3_PTX_DRX_N8 USB3_PTX_DRX_P1 USB3_PTX_DRX_P6 USB3_PTX_DRX_P7 USB3_PTX_DRX_P8 USB3_PTX_L_DRX_N6 USB3_PTX_L_DRX_P6
net group VREF: nets +V_DDR_REFA +V_DDR_REFA_R +V_DDR_REFB +V_DDR_REFB_R
net group XDP: nets XDP_TMS
nets with their own width: min track width 0.127; nets TP_LED_EN
nets with their own width: min track width 0.254; nets +1V8_AON +VDD18 ECAGND
nets with their own width: min track width 0.381; nets USB2_COMP XCLK_BIASREF
nets with their own width: min track width 0.508; nets +0.9V_DP +0.9V_PCIE +1.2V_DDR +1VALW +3VALW +3VS +5VALW +5VS +VCC_CORE +VCCGT +VCCIO +VCCSA ALIEN_LED_B_DRV# ALIEN_LED_G_DRV# ALIEN_LED_R_DRV# B+ B+_BIAS BATT_CHG_LED BATT_CHG_LED# BATT_LOW_LED BATT_LOW_LED# EN_TPLED GND GNDA LAN_LED2# LAN_LED2#_R LOGO_LED_B_DRV# LOGO_LED_G_DRV# LOGO_LED_R_DRV# N21000719 N124752685 N124753277 POK PWR_B_7313# PWR_G_7313# PWR_LED# PWR_R_7313# VSB_N_001 VSB_N_002 VSB_N_003
nets with their own width: min track width 1.016; nets ISENSEP_L ISENSEP_L_R ISENSEP_R ISENSEP_R_R IVSENSE_L IVSENSE_R LINE1_L LINE1_R RJ45_CT VSENSEN_L VSENSEN_R
nets with their own width: min track width 1.524; nets +5V_HDD

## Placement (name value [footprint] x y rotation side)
C2  0.1U_0402_10V6K  [C_0402]  194.81 12.37 0 top
C3  2200P_0402_25V7K  [C_0402]  128.04 105.44 180 bottom
C4  1U_0402_6.3V6K  [C_0402]  177.43 76.27 270 top
C6  0.1U_0402_10V7K  [C_0402]  178.42 84.17 0 top
C7  1U_0402_6.3V6K  [C_0402]  182.04 79.02 0 top
C8  22U_0805_6.3V6M  [C_0805]  173.96 98.73 180 top
C10  0.1U_0402_10V7K  [C_0402]  181.54 84.13 0 top
C11  2.2U_0402_6.3VX5R  [C_0402]  130.11 104.02 270 bottom
C29  0.1U_0402_16V4Z  [C_0402]  207.26 6.85 0 top
C256  10U_0402_6.3V6M  [C_0402]  58.09 11.46 180 bottom
C257  10U_0603_6.3V6M  [C_0603]  58.29 12.53 180 bottom
C258  0.1U_0402_16V7K  [C_0402]  65.39 18.72 90 bottom
C260  10U_0402_6.3V6M  [C_0402]  72.13 13.47 0 bottom
C261  10U_0603_6.3V6M  [C_0603]  71.6 12.41 0 bottom
C262  10U_0603_6.3V6M  [C_0603]  67.61 19.01 0 bottom
C263  0.1U_0402_10V7K  [C_0402]  67.98 20.07 0 bottom
C264  10U_0603_6.3V6M  [C_0603]  59.93 18.01 180 bottom
C265  0.1U_0402_10V7K  [C_0402]  59.76 19.08 180 bottom
C266  10U_0402_6.3V6M  [C_0402]  223.34 41.57 90 top
C267  10U_0603_6.3V6M  [C_0603]  222.26 41.27 90 top
C268  0.01U_0402_16V  [C_0402]  224.34 47.25 0 top
C269  10U_0603_6.3V6M  [C_0603]  223.69 45.26 180 top
C270  0.1U_0402_10V7K  [C_0402]  223.69 43.99 180 top
C617  33P_0402_50V8J  [C_0402]  333.78 49 180 top
C618  33P_0402_50V8J  [C_0402]  333.78 48.11 180 top
C620  33P_0402_50V8J  [C_0402]  276.37 25.01 180 top
C621  0.047U_0402_16V4Z  [C_0402]  331.55 32.18 180 top
C622  22U_0402_6.3V6M  [C_0402]  333.38 50.13 90 top
C623  0.047U_0402_16V4Z  [C_0402]  331.55 33.06 180 top
C624  22U_0402_6.3V6M  [C_0402]  321.5 26.76 270 top
C625  0.047U_0402_16V4Z  [C_0402]  276.37 22.22 180 top
C627  0.047U_0402_16V4Z  [C_0402]  276.37 24.06 180 top
C628  33P_0402_50V8J  [C_0402]  276.37 23.1 180 top
C629  33P_0402_50V8J  [C_0402]  250.01 7.75 270 top
C630  33P_0402_50V8J  [C_0402]  253.82 7.75 270 top
C631  150U_B2_6.3VM_R35M  [C_B2]  260.32 18.28 180 bottom
C632  0.047U_0402_16V4Z  [C_0402]  252.87 7.75 270 top
C633  22U_0402_6.3V6M  [C_0402]  258.45 14.57 90 bottom
C634  0.047U_0402_16V4Z  [C_0402]  250.96 7.75 270 top
C635  22U_0402_6.3V6M  [C_0402]  333.75 33.52 0 top
C636  22U_0402_6.3V6M  [C_0402]  333.75 32.63 0 top
C637  22U_0402_6.3V6M  [C_0402]  333.75 31.74 0 top
C638  22U_0402_6.3V6M  [C_0402]  241.63 8.3 90 top
C639  22U_0402_6.3V6M  [C_0402]  242.52 8.3 90 top
C640  22U_0402_6.3V6M  [C_0402]  243.4 8.3 90 top
C641  150U_B2_6.3VM_R35M  [C_B2]  260.57 14.43 180 bottom
C2498  0.1U_0402_10V6K  [C_0402]  184.73 48.62 90 bottom
C2500  2200P_0402_25V7K  [C_0402]  140.47 132.51 90 bottom
C2502  2200P_0402_25V7K  [C_0402]  185.94 49.97 90 bottom
C2504  2200P_0402_25V7K  [C_0402]  187.79 49.01 180 bottom
C2505  2200P_0402_25V7K  [C_0402]  275.28 129.49 0 top
C2506  220P_0402_50V8J  [C_0402]  64.28 13.64 270 bottom
C2507  470P_0402_50V7K  [C_0402]  65.2 13.64 270 bottom
C2508  1U_0402_6.3V  [C_0402]  201.82 8.18 180 top
C2509  0.1U_0402_25V6K~D  [C_0402]  207.26 8.63 0 top
C2510  2200P_0402_25V7K  [C_0402]  189.18 45.74 270 bottom
C2511  2200P_0402_25V7K  [C_0402]  285.62 38.09 0 bottom
C2512  10U_0603_6.3V6M  [C_0603]  232.05 8.79 180 bottom
C2513  47U_0603_6.3V6M  [C_0603]  232.05 7.5 180 bottom
C2514  10U_0603_6.3V6M  [C_0603]  266.98 24.83 90 bottom
C2515  10U_0603_6.3V6M  [C_0603]  267.43 23.35 270 bottom
C2516  0.1U_0402_10V7K  [C_0402]  266.96 20.36 0 bottom
C2518  0.1U_0402_10V7K  [C_0402]  128.88 99.69 90 top
C2519  0.1U_0402_10V7K  [C_0402]  126.72 99.25 90 bottom
C2520  0.1U_0402_10V7K  [C_0402]  183.82 79.04 270 top
C2521  0.1U_0402_10V7K  [C_0402]  177.81 79.18 270 top
C2522  0.1U_0402_10V7K  [C_0402]  228.6 43.92 270 top
C2523  0.1U_0402_10V7K  [C_0402]  63.39 13.64 270 bottom
C2524  0.1U_0402_10V7K  [C_0402]  66.07 13.64 270 bottom
C2525  0.1U_0402_10V7K  [C_0402]  62.18 19.41 180 bottom
CA1  4.7U_0402_6.3V6M  [C_0402]  33.85 25.83 0 bottom
CA2  0.1U_0402_16V7K  [C_0402]  33.85 26.72 0 bottom
CA3  10U_0603_6.3V6M  [C_0603]  30.56 38.59 0 bottom
CA4  0.1U_0402_16V7K  [C_0402]  30.81 37.52 0 bottom
CA5  10U_0603_6.3V6M  [C_0603]  28.9 41.52 90 bottom
CA6  0.1U_0402_16V7K  [C_0402]  27.82 41.44 90 bottom
CA7  10U_0603_6.3V6M  [C_0603]  33.36 38.59 180 top
CA8  0.1U_0402_16V7K  [C_0402]  33.12 37.52 180 top
CA9  10U_0603_6.3V6M  [C_0603]  33.36 39.8 180 top
CA10  0.1U_0402_16V7K  [C_0402]  33.12 40.88 180 top
CA11  10P_0402_50V8J  [C_0402]  38.5 29.65 180 top
CA12  0.1U_0402_16V7K  [C_0402]  37.49 32.36 90 bottom
CA13  4.7U_0402_6.3V6M  [C_0402]  38.38 32.36 90 bottom
CA14  10U_0603_6.3V6M  [C_0603]  29.17 38.34 180 bottom
CA15  0.1U_0402_16V7K  [C_0402]  28.74 37.26 180 bottom
CA16  0.1U_0402_16V7K  [C_0402]  29.42 26.86 270 top
CA17  10U_0603_6.3V6M  [C_0603]  28.34 26.85 270 top
CA19  0.1U_0402_16V7K  [C_0402]  32.44 23.1 0 top
CA20  2.2U_0402_6.3V6M  [C_0402]  30.76 26.66 180 bottom
CA21  2.2U_0402_6.3V6M  [C_0402]  29.37 25.77 180 bottom
CA23  0.1U_0402_16V7K  [C_0402]  33.98 26.8 270 top
CA24  2.2U_0402_6.3V6M  [C_0402]  28.58 31.12 270 top
CA25  2.2U_0402_6.3V6M  [C_0402]  28.48 28.45 90 top
CA26  0.1U_0402_16V7K  [C_0402]  27.34 36.31 180 bottom
CA27  2.2U_0402_6.3V6M  [C_0402]  27.34 35.42 180 bottom
CA28  0.1U_0402_16V7K  [C_0402]  32.55 26.66 180 bottom
CA29  10U_0603_6.3V6M  [C_0603]  32.71 25.52 180 bottom
CA30  0.1U_0402_16V7K  [C_0402]  31.2 26.73 270 top
CA31  4.7U_0603_6.3V6M  [C_0603]  32.28 26.66 270 top
CA32  10U_0603_6.3V6M  [C_0603]  28.98 37.2 180 top
CA33  10U_0603_6.3V6M  [C_0603]  27.02 34.37 180 bottom
CA34  10P_0402_50V8J  [C_0402]  36.76 38.85 0 bottom
CA35  10P_0402_50V8J  [C_0402]  36.76 37.52 0 bottom
CA41  0.1U_0402_10V7K  [C_0402]  37.47 31.48 0 bottom
CA42  100P_0201_50V8J  [C_0201]  23.67 21.45 180 bottom
CA43  100P_0201_50V8J  [C_0201]  19.02 17.51 180 bottom
CA44  0.01U_0201_16V7  [C_0201]  17.79 26.04 270 top
CA45  680P_0402_50V8J  [C_0402]  27.82 21.28 270 bottom
CA46  680P_0402_50V8J  [C_0402]  28.71 19.54 90 bottom
CA47  330U_D2E_6.3VM_R25M  [C_D2E]  25.41 29.65 270 bottom
CA48  100P_0201_50V8J  [C_0201]  21.18 24.36 270 top
CA49  330U_D2E_6.3VM_R25M  [C_D2E]  20.65 29.65 270 bottom
CA50  100P_0201_50V8J  [C_0201]  21.12 25.92 180 top
CA51  0.01U_0201_16V7  [C_0201]  22.04 28.02 90 top
CA52  10U_0603_25V6M  [C_0603]  38.24 8.56 180 bottom
CA53  0.1U_0402_25V7K  [C_0402]  38.93 8.83 270 top
CA54  1000P_0402_50V7K  [C_0402]  38.16 6.77 0 top
CA55  10U_0603_25V6M  [C_0603]  29.16 6.66 180 top
CA56  0.1U_0402_25V7K  [C_0402]  30.87 7.98 90 bottom
CA57  1000P_0402_50V7K  [C_0402]  29.23 7.74 180 top
CA58  10U_0402_6.3V6M  [C_0402]  36.9 17.19 90 top
CA59  0.1U_0402_16V7K  [C_0402]  36.01 17.19 90 top
CA60  0.1U_0402_16V7K  [C_0402]  35.12 17.19 90 top
CA61  10U_0603_25V6M  [C_0603]  28.33 11.8 0 bottom
CA62  0.1U_0402_25V7K  [C_0402]  27.75 12.14 270 top
CA63  1000P_0402_50V7K  [C_0402]  28.64 12.14 270 top
CA64  10U_0402_6.3V6M  [C_0402]  36.51 16.76 0 bottom
CA65  0.1U_0402_16V7K  [C_0402]  36.51 17.65 0 bottom
CA66  1U_0402_16V6K  [C_0402]  27.87 9.9 0 top
CA67  .033U_0603_50V7  [C_0603]  39.52 7.82 45 bottom
CA68  .033U_0603_50V7  [C_0603]  36.13 5.84 180 top
CA69  .033U_0603_50V7  [C_0603]  32.39 5.94 0 top
CA70  .033U_0603_50V7  [C_0603]  27.69 8.82 0 top
CA71  1U_0402_16V6K  [C_0402]  38.37 10.54 180 bottom
CA74  0.1U_0402_16V7K  [C_0402]  33.85 16.81 90 bottom
CA77  10U_0402_6.3V6M  [C_0402]  35.25 15.31 270 bottom
CA78  0.1U_0402_16V7K  [C_0402]  34.37 15.31 270 bottom
CA79  10U_0603_25V6M  [C_0603]  33.73 7.42 90 bottom
CA80  0.1U_0402_25V7K  [C_0402]  34.81 7.72 90 bottom
CA81  1000P_0402_50V7K  [C_0402]  35.7 7.72 90 bottom
CA82  10U_0603_25V6M  [C_0603]  29.79 7.99 90 bottom
CA83  0.1U_0402_25V7K  [C_0402]  31.76 7.53 90 bottom
CA84  1000P_0402_50V7K  [C_0402]  32.65 7.53 90 bottom
CA85  10U_0402_6.3V6M  [C_0402]  35.31 26.8 270 top
CA87  330P_0402_50V7  [C_0402]  38.22 6.47 0 bottom
CA88  330P_0402_50V7  [C_0402]  36.19 4.79 180 top
CA89  330P_0402_50V7  [C_0402]  33.52 4.75 0 top
CA90  330P_0402_50V7  [C_0402]  31 5.15 270 top
CA91  680P_0402_50V8J  [C_0402]  18.37 18.6 270 top
CA92  680P_0402_50V8J  [C_0402]  18.25 21.38 90 top
CA254  1000P_0402_50V7K  [C_0402]  38.24 5.02 90 top
CA255  1000P_0402_50V7K  [C_0402]  35.84 6.02 180 bottom
CA256  1000P_0402_50V7K  [C_0402]  32.95 3.25 0 top
CA257  1000P_0402_50V7K  [C_0402]  29.98 5.15 270 top
CA258  10P_0402_50V8J  [C_0402]  37.52 29.49 270 bottom
CA259  0.1U_0402_16V7K  [C_0402]  26.3 38.15 90 top
CA260  0.1U_0402_16V7K  [C_0402]  23.71 35.33 180 top
CA261  0.1U_0402_16V7K  [C_0402]  31 28.63 90 top
CC1  0.22U_0201_6.3V  [C_0201]  217.14 122.48 0 bottom
CC2  0.22U_0201_6.3V  [C_0201]  215.87 123.37 0 bottom
CC3  0.22U_0201_6.3V  [C_0201]  216.7 125.4 0 bottom
CC4  0.22U_0201_6.3V  [C_0201]  214.98 126.42 0 bottom
CC5  0.22U_0201_6.3V  [C_0201]  216.25 126.93 0 bottom
CC6  0.22U_0201_6.3V  [C_0201]  214.98 128.39 0 bottom
CC7  0.22U_0201_6.3V  [C_0201]  216.25 129.38 0 bottom
CC8  0.22U_0201_6.3V  [C_0201]  214.92 130.36 0 bottom
CC9  0.22U_0201_6.3V  [C_0201]  153.93 173.66 90 bottom
CC10  0.22U_0201_6.3V  [C_0201]  155.14 175.57 90 bottom
CC11  0.22U_0201_6.3V  [C_0201]  156.34 173.67 90 bottom
CC12  0.22U_0201_6.3V  [C_0201]  157.78 175.56 90 bottom
CC13  0.22U_0201_6.3V  [C_0201]  217.14 121.91 0 bottom
CC14  0.22U_0201_6.3V  [C_0201]  215.87 122.8 0 bottom
CC15  0.22U_0201_6.3V  [C_0201]  216.7 124.83 0 bottom
CC16  0.22U_0201_6.3V  [C_0201]  214.98 125.85 0 bottom
CC17  0.22U_0201_6.3V  [C_0201]  216.25 127.5 0 bottom
CC18  0.22U_0201_6.3V  [C_0201]  214.98 127.82 0 bottom
CC19  0.22U_0201_6.3V  [C_0201]  216.25 128.71 0 bottom
CC20  0.22U_0201_6.3V  [C_0201]  214.92 129.78 0 bottom
CC21  0.22U_0201_6.3V  [C_0201]  153.04 173.66 90 bottom
CC22  0.22U_0201_6.3V  [C_0201]  154.25 175.57 90 bottom
CC23  0.22U_0201_6.3V  [C_0201]  155.45 173.67 90 bottom
CC24  0.22U_0201_6.3V  [C_0201]  156.86 175.56 90 bottom
CC36  1U_0201_6.3V6M  [C_0201]  170.66 102.17 0 top
CC37  1U_0201_6.3V6M  [C_0201]  170.66 102.75 0 top
CC39  22U_0402_6.3V6M  [C_0402]  168.23 116.28 180 top
CD1  1U_0402_6.3V6K~D  [C_0402]  173.12 62.19 270 top
CD2  1U_0402_6.3V6K~D  [C_0402]  164.66 62.23 270 top
CD3  1U_0402_6.3V6K~D  [C_0402]  179.27 62.43 0 top
CD4  1U_0402_6.3V6K~D  [C_0402]  179.27 61.54 0 top
CD5  10U_0603_6.3V6M~D  [C_0603]  150.01 62.37 270 top
CD6  10U_0603_6.3V6M~D  [C_0603]  143.91 62.37 270 top
CD7  10U_0603_6.3V6M~D  [C_0603]  139.91 62.37 270 top
CD8  10U_0603_6.3V6M~D  [C_0603]  139.47 53.03 90 top
CD9  10U_0603_6.3V6M~D  [C_0603]  179.03 63.51 0 top
CD10  10U_0603_6.3V6M~D  [C_0603]  179.03 64.72 0 top
CD11  220U_D7_2VM_R6M  [C_EEFSS0D221R]  163 75.87 0 top
CD12  1U_0402_6.3V6K~D  [C_0402]  178.4 50.87 180 top
CD13  10U_0603_6.3V6M~D  [C_0603]  179.46 52.57 0 top
CD14  10U_0603_6.3V6M~D  [C_0603]  178.84 49.79 180 top
CD15  10U_0603_6.3V6M~D  [C_0603]  179.46 53.84 0 top
CD16  0.1U_0402_16V7K~D  [C_0402]  176.63 64.65 180 top
CD17  2.2U_0603_6.3V6K~D  [C_0603]  176.87 65.73 180 top
CD18  0.1U_0402_16V7K~D  [C_0402]  154.45 53.15 90 top
CD19  1U_0402_6.3V6K~D  [C_0402]  134.07 48.75 90 top
CD20  1U_0402_6.3V6K~D  [C_0402]  163.21 49.49 270 top
CD21  1U_0402_6.3V6K~D  [C_0402]  135.96 41.81 90 top
CD22  1U_0402_6.3V6K~D  [C_0402]  114.44 41.21 270 top
CD23  10U_0603_6.3V6M~D  [C_0603]  140.48 40.27 90 top
CD24  10U_0603_6.3V6M~D  [C_0603]  150.2 49.54 270 top
CD25  10U_0603_6.3V6M~D  [C_0603]  153.82 49.54 270 top
CD26  10U_0603_6.3V6M~D  [C_0603]  143.21 40.27 90 top
CD27  10U_0603_6.3V6M~D  [C_0603]  180.3 49.98 0 top
CD28  10U_0603_6.3V6M~D  [C_0603]  180.3 51.19 0 top
CD29  0.1U_0402_16V7K~D  [C_0402]  154.44 41.22 0 top
CD30  1U_0402_6.3V6K~D  [C_0402]  180.54 48.9 0 top
CD31  1U_0402_6.3V6K~D  [C_0402]  180.54 48.01 0 top
CD32  1U_0402_6.3V6K~D  [C_0402]  179.67 41.79 180 top
CD33  220U_D7_2VM_R6M  [C_EEFSS0D221R]  159.11 75.87 180 top
CD34  0.1U_0402_16V7K~D  [C_0402]  177.57 47.55 180 top
CD35  2.2U_0603_6.3V6K~D  [C_0603]  178.26 48.59 180 top
CD69  0.1U_0402_16V7K~D  [C_0402]  137.43 54.06 270 top
CD70  10U_0603_6.3V6M~D  [C_0603]  153.44 62.37 270 top
CD71  10U_0603_6.3V6M~D  [C_0603]  150.31 53.01 90 top
CD72  10U_0603_6.3V6M~D  [C_0603]  151.91 53.03 90 top
CD73  10U_0603_6.3V6M~D  [C_0603]  140.92 54.03 90 top
CD74  1U_0402_6.3V6K~D  [C_0402]  168.49 54.12 270 top
CD75  1U_0402_6.3V6K~D  [C_0402]  123.4 61.37 90 top
CD76  1U_0402_6.3V6K~D  [C_0402]  135.47 53.15 90 top
CD77  1U_0402_6.3V6K~D  [C_0402]  157.94 54.12 270 top
CD78  1U_0402_6.3V6K~D  [C_0402]  130.13 62.31 270 top
CD79  1U_0402_6.3V6K~D  [C_0402]  119.53 62.25 270 top
CD80  1U_0402_6.3V6K~D  [C_0402]  158.01 40.38 90 top
CD81  1U_0402_6.3V6K~D  [C_0402]  166.4 48.47 90 top
CD82  1U_0402_6.3V6K~D  [C_0402]  167.62 48.47 90 top
CD83  1U_0402_6.3V6K~D  [C_0402]  116.11 53.04 0 top
CD84  10U_0603_6.3V6M~D  [C_0603]  140.66 49.58 270 top
CD85  10U_0603_6.3V6M~D  [C_0603]  146.38 46.85 0 top
CD86  10U_0603_6.3V6M~D  [C_0603]  151.59 40.27 90 top
CD87  10U_0603_6.3V6M~D  [C_0603]  139.26 49.58 270 top
CD88  10U_0603_6.3V6M~D  [C_0603]  179.98 40.71 180 top
CD89  10U_0603_6.3V6M~D  [C_0603]  179.98 38.17 180 top
CD90  10U_0603_6.3V6M~D  [C_0603]  179.98 39.38 180 top
CD91  0.1U_0402_16V7K~D  [C_0402]  138.18 51.57 270 top
CD92  0.1U_0402_16V7K~D  [C_0402]  139.07 51.57 270 top
CE1  0.1U_0402_16V4Z  [C_0402]  322.45 18.15 0 top
CE2  15P_0402_50V  [C_0402]  319.24 6.59 180 top
CE5  15P_0402_50V  [C_0402]  319.24 8.06 180 top
CE6  0.1U_0402_16V4Z  [C_0402]  313.58 9.39 180 top
CE7  1U_0402_6.3V  [C_0402]  323.41 10.71 90 top
CE8  0.1U_0402_16V7K  [C_0402]  319.24 8.94 180 top
CE19  0.1U_0402_16V4Z~D  [C_0402]  103.69 27.21 0 bottom
CE20  22P_0402_50V8J~D  [C_0402]  101.09 27.32 90 bottom
CE22  4.7U_0603_10V  [C_0603]  104.29 31.97 270 bottom
CE24  0.1U_0402_16V4Z  [C_0402]  225.19 160.33 180 top
CE25  0.1U_0402_16V4Z  [C_0402]  188.6 25.86 90 top
CE27  0.1U_0402_16V7K  [C_0402]  309.11 17.62 0 top
CE28  0.1U_0402_10V7K  [C_0402]  289.87 10.1 270 top
CE29  0.1U_0402_10V7K  [C_0402]  297.05 27.71 90 top
CE30  0.1U_0402_10V7K  [C_0402]  303.02 27.71 90 top
CE31  1000P_0402_50V7K  [C_0402]  287.7 26.28 0 top
CE32  1000P_0402_50V7K  [C_0402]  309.17 24.85 270 top
CE33  0.1U_0402_10V7K  [C_0402]  287.45 12.88 0 top
CE34  0.047U_0402_16V4Z  [C_0402]  300.36 27.85 90 top
CE35  100P_0402_50V8J  [C_0402]  288.71 11.88 0 top
CE36  0.1U_0402_10V7K  [C_0402]  301.25 27.73 90 top
CE38  0.1U_0402_10V7K  [C_0402]  309.11 21.31 0 top
CE40  100P_0402_50V8J  [C_0402]  310.02 15.59 180 top
CE41  0.1U_0402_10V7K  [C_0402]  303.91 27.71 90 top
CE42  0.1U_0402_10V7K  [C_0402]  304.99 7.88 270 top
CE43  0.1U_0402_10V7K  [C_0402]  309.11 19.53 0 top
CE44  0.1U_0402_10V7K  [C_0402]  293.11 27.28 90 top
CE45  0.1U_0402_10V7K  [C_0402]  298.7 30.22 0 top
CE46  0.1U_0402_10V7K  [C_0402]  296.36 8.4 270 top
CE51  0.033U_0402_25V  [C_0402]  309.76 11.94 270 top
CE55  0.1U_0402_16V7K~D  [C_0402]  331.42 40.11 90 top
CE56  0.1U_0402_16V4Z  [C_0402]  327.68 43.87 180 top
CE59  0.1U_0402_16V4Z  [C_0402]  313.52 21.26 180 top
CE60  0.1U_0402_16V4Z  [C_0402]  310.65 11.94 270 top
CE61  0.1U_0402_16V4Z  [C_0402]  219.91 167.57 270 bottom
CE62  0.1U_0402_16V4Z  [C_0402]  313.83 57.53 180 top
CE63  0.1U_0402_16V7K~D  [C_0402]  315.4 56.06 0 top
CE64  0.1U_0402_16V7K  [C_0402]  103.69 28.12 0 bottom
CE65  10U_0402_6.3V6M  [C_0402]  103.69 29.01 0 bottom
CE79  0.1U_0402_10V6K  [C_0402]  144.8 168.41 0 top
CE80  4.7U_0805_10V4Z  [C_0805]  143.14 166.59 90 top
CE81  0.1U_0402_10V6K  [C_0402]  153.36 165.01 90 top
CE82  0.1U_0402_10V6K  [C_0402]  143.6 165.04 180 top
CE84  0.1U_0402_16V4Z  [C_0402]  44.38 49.2 0 bottom
CE85  0.1U_0402_16V4Z  [C_0402]  33.36 50.6 180 bottom
CE86  0.1U_0402_16V4Z  [C_0402]  284.54 32.95 0 bottom
CE87  0.1U_0402_16V4Z  [C_0402]  275.6 34.14 90 bottom
CE168  0.1U_0402_16V4Z  [C_0402]  301.9 37.2 180 top
CE169  0.1U_0402_16V4Z  [C_0402]  316.04 28.57 0 top
CE170  1U_0402_6.3V  [C_0402]  312.11 28.58 270 top
CF4  22U_0603_6.3V6M  [C_0603]  107.58 62.83 270 top
CF5  22U_0805_6.3VAM  [C_0805]  290.39 75.86 180 top
CG1  0.1U_0201_6.3V6K  [C_0201]  197.4 105.87 90 bottom
CG2  1U_0402_6.3V6K  [C_0402]  234.78 115.97 180 top
CG3  1U_0402_6.3V6K  [C_0402]  234.5 117.85 0 top
CG4  1U_0402_6.3V6K  [C_0402]  234.69 111.99 0 top
CG5  4.7U_0603_6.3V6M  [C_0603]  233.94 118.93 0 top
CG6  10U_0603_6.3V6M  [C_0603]  232.23 119.88 270 top
CG7  22U_0805_6.3V6M  [C_0805]  240.78 109.88 0 top
CG8  0.22U_0201_6.3V  [C_0201]  206.98 134.1 0 top
CG9  0.22U_0201_6.3V  [C_0201]  206.98 134.67 0 top
CG10  0.22U_0201_6.3V  [C_0201]  205.71 135.12 0 top
CG11  4.7U_0603_6.3V6M  [C_0603]  225.75 108.83 90 top
CG12  10U_0603_6.3V6M  [C_0603]  227.15 104.07 90 top
CG13  1U_0402_6.3V6K  [C_0402]  243.15 111.36 90 top
CG14  4.7U_0603_6.3V6M  [C_0603]  233.94 120.13 0 top
CG16  0.22U_0201_6.3V  [C_0201]  205.71 135.69 0 top
CG17  1U_0402_6.3V6K  [C_0402]  226.75 108.75 0 top
CG18  1U_0402_6.3V6K  [C_0402]  225.45 104.64 180 top
CG19  1U_0402_6.3V6K  [C_0402]  238.9 110.37 270 top
CG20  4.7U_0603_6.3V6M  [C_0603]  222.96 120.58 180 top
CG21  10U_0603_6.3V6M  [C_0603]  221.56 121.78 0 top
CG22  0.22U_0201_6.3V  [C_0201]  206.98 136.07 0 top
CG23  1U_0402_6.3V6K  [C_0402]  236.86 111.93 90 top
CG24  22U_0603_6.3V6M  [C_0603]  217.47 108.51 0 top
CG25  0.22U_0201_6.3V  [C_0201]  206.98 136.64 0 top
CG26  0.22U_0201_6.3V  [C_0201]  205.77 136.9 0 top
CG27  0.22U_0201_6.3V  [C_0201]  205.77 137.47 0 top
CG28  0.22U_0201_6.3V  [C_0201]  206.98 137.79 0 top
CG29  0.22U_0201_6.3V  [C_0201]  206.98 138.36 0 top
CG30  0.22U_0201_6.3V  [C_0201]  205.77 138.67 0 top
CG31  0.22U_0201_6.3V  [C_0201]  205.77 139.25 0 top
CG32  0.22U_0201_6.3V  [C_0201]  206.98 139.5 0 top
CG33  0.22U_0201_6.3V  [C_0201]  206.98 140.07 0 top
CG34  0.1U_0201_6.3V6K  [C_0201]  218.98 112.26 0 top
CG35  0.22U_0201_6.3V  [C_0201]  205.9 141.02 0 top
CG36  0.22U_0201_6.3V  [C_0201]  205.9 141.6 0 top
CG40  0.1U_0402_10V7K  [C_0402]  242.97 114.29 0 top
CG42  4.7U_0402_6.3V6M  [C_0402]  234.78 113.08 180 top
CG43  4.7U_0402_6.3V6M  [C_0402]  234.78 115.09 180 top
CG47  0.1U_0402_10V7K  [C_0402]  229.05 118.02 90 top
CG48  0.1U_0402_10V7K  [C_0402]  231.14 109.72 0 top
CG49  0.1U_0402_10V7K  [C_0402]  228.16 118.02 90 top
CG51  0.1U_0402_10V7K  [C_0402]  228.42 110.49 270 top
CG53  0.1U_0402_10V7K  [C_0402]  233.83 109.72 180 top
CG54  0.1U_0402_16V7K  [C_0402]  229.69 90.59 90 top
CG55  22U_0603_6.3V6M  [C_0603]  204.03 107.01 270 top
CG56  0.1U_0402_16V4Z~D  [C_0402]  244.5 90.61 180 top
CG57  0.1U_0402_16V4Z~D  [C_0402]  246.71 105.29 270 top
CG58  0.1U_0402_16V4Z~D  [C_0402]  226.93 94.94 270 top
CG59  0.1U_0402_10V7K  [C_0402]  202.95 106.75 270 top
CG60  0.1U_0402_10V7K  [C_0402]  237.56 90.59 90 top
CG61  100P_0402_50V8J~D  [C_0402]  192.99 122.28 90 bottom
CG62  10U_0603_6.3V6M  [C_0603]  189.75 114.61 0 bottom
CG63  10U_0603_6.3V6M  [C_0603]  187.52 119.05 270 bottom
CG64  220P_0402_50V8J  [C_0402]  196.16 110.86 270 bottom
CG65  220P_0402_50V8J  [C_0402]  197.37 110.86 270 bottom
CG66  0.1U_0402_16V4Z  [C_0402]  211.83 107.37 0 bottom
CG75  22P_0402_50V8J  [C_0402]  212.23 120.53 270 bottom
CG76  22P_0402_50V8J  [C_0402]  212.23 117.45 90 bottom
CG78  820P_0402_25V7  [C_0402]  276.86 101.95 180 bottom
CG79  820P_0402_25V7  [C_0402]  276.54 105.65 0 bottom
CG80  22U_0603_6.3V6M  [C_0603]  283.54 86.6 180 bottom
CG81  22U_0603_6.3V6M  [C_0603]  285.25 113.78 270 bottom
CG82  22U_0603_6.3V6M  [C_0603]  278.51 86.6 180 bottom
CG83  10U_0402_6.3V4Z  [C_0402]  272.44 101.65 180 bottom
CG84  10U_0402_6.3V4Z  [C_0402]  278.66 101.65 180 bottom
CG85  10U_0402_6.3V4Z  [C_0402]  280.16 101.65 0 bottom
CG86  1U_0402_6.3V4Z  [C_0402]  278.72 120.64 180 bottom
CG87  1U_0402_6.3V4Z  [C_0402]  270.66 101.65 180 bottom
CG88  1U_0402_6.3V4Z  [C_0402]  272.63 105.65 180 bottom
CG89  1U_0402_6.3V4Z  [C_0402]  281.01 106.1 180 top
CG90  1U_0402_6.3V4Z  [C_0402]  273.62 92.45 0 top
CG91  1U_0402_6.3V4Z  [C_0402]  277.57 91.61 90 top
CG97  22U_0603_6.3V6M  [C_0603]  285.25 117.53 90 bottom
CG98  22U_0603_6.3V6M  [C_0603]  280.93 105.46 0 bottom
CG99  22U_0603_6.3V6M  [C_0603]  272.86 111.56 0 top
CG100  10U_0402_6.3V4Z  [C_0402]  279.59 120.64 0 bottom
CG101  10U_0402_6.3V4Z  [C_0402]  281.36 120.64 0 bottom
CG102  10U_0402_6.3V4Z  [C_0402]  270.85 105.65 180 bottom
CG103  1U_0402_6.3V4Z  [C_0402]  283.14 120.64 0 bottom
CG104  1U_0402_6.3V4Z  [C_0402]  279.4 86.67 0 bottom
CG105  1U_0402_6.3V4Z  [C_0402]  279.87 93.4 180 top
CG106  1U_0402_6.3V4Z  [C_0402]  281.64 101.08 180 top
CG113  820P_0402_25V7  [C_0402]  276.35 70.73 0 bottom
CG114  820P_0402_25V7  [C_0402]  263.09 60.37 90 bottom
CG115  22U_0603_6.3V6M  [C_0603]  285.19 76.95 270 bottom
CG116  22U_0603_6.3V6M  [C_0603]  285.19 73.71 270 bottom
CG117  22U_0603_6.3V6M  [C_0603]  272.49 102.73 0 bottom
CG118  10U_0402_6.3V4Z  [C_0402]  281.05 85.53 0 bottom
CG119  10U_0402_6.3V4Z  [C_0402]  279.27 85.53 0 bottom
CG120  10U_0402_6.3V4Z  [C_0402]  279.4 70.67 0 bottom
CG121  1U_0402_6.3V4Z  [C_0402]  272.31 70.73 180 bottom
CG122  1U_0402_6.3V4Z  [C_0402]  270.53 70.73 180 bottom
CG123  1U_0402_6.3V4Z  [C_0402]  263.09 58.59 90 bottom
CG124  1U_0402_6.3V4Z  [C_0402]  253.82 65.83 90 top
CG125  1U_0402_6.3V4Z  [C_0402]  262.77 60.18 90 top
CG126  1U_0402_6.3V4Z  [C_0402]  248.1 59.06 270 bottom
CG132  22U_0603_6.3V6M  [C_0603]  251.09 52.06 180 bottom
CG133  22U_0603_6.3V6M  [C_0603]  259.85 52 180 bottom
CG134  22U_0603_6.3V6M  [C_0603]  247.91 55.87 90 bottom
CG135  10U_0402_6.3V4Z  [C_0402]  249.34 66.79 270 top
CG136  10U_0402_6.3V4Z  [C_0402]  248.1 54.93 270 bottom
CG137  10U_0402_6.3V4Z  [C_0402]  248.55 55.06 270 top
CG138  1U_0402_6.3V4Z  [C_0402]  271.48 76.57 180 top
CG139  1U_0402_6.3V4Z  [C_0402]  257.31 64.33 270 top
CG140  1U_0402_6.3V4Z  [C_0402]  279.19 71.3 0 top
CG141  1U_0402_6.3V4Z  [C_0402]  262.45 57.28 270 top
CG148  820P_0402_25V7  [C_0402]  228.04 60.37 90 bottom
CG149  820P_0402_25V7  [C_0402]  232.1 60.18 90 bottom
CG150  22U_0603_6.3V6M  [C_0603]  233.18 55.3 270 top
CG151  22U_0603_6.3V6M  [C_0603]  242.17 53.43 180 top
CG152  22U_0603_6.3V6M  [C_0603]  227.08 65.84 90 top
CG153  10U_0402_6.3V4Z  [C_0402]  237.82 64.39 270 top
CG154  10U_0402_6.3V4Z  [C_0402]  245.82 63.41 90 top
CG155  10U_0402_6.3V4Z  [C_0402]  232.1 64.81 90 bottom
CG156  1U_0402_6.3V4Z  [C_0402]  233.12 66.4 90 top
CG157  1U_0402_6.3V4Z  [C_0402]  245.82 66.68 270 top
CG158  1U_0402_6.3V4Z  [C_0402]  245.82 57.98 270 top
CG159  1U_0402_6.3V4Z  [C_0402]  244.24 52.12 180 bottom
CG160  1U_0402_6.3V4Z  [C_0402]  235.16 52.12 180 bottom
CG161  1U_0402_6.3V4Z  [C_0402]  219.03 52.12 180 bottom
CG167  22U_0603_6.3V6M  [C_0603]  221.37 53.33 90 top
CG168  22U_0603_6.3V6M  [C_0603]  247.39 89.73 135 top
CG169  22U_0603_6.3V6M  [C_0603]  222.07 65.65 90 top
CG170  10U_0402_6.3V4Z  [C_0402]  218.93 63.43 270 top
CG171  10U_0402_6.3V4Z  [C_0402]  219.67 55.52 270 top
CG172  10U_0402_6.3V4Z  [C_0402]  232.1 66.59 90 bottom
CG173  1U_0402_6.3V4Z  [C_0402]  237.82 65.95 90 top
CG174  1U_0402_6.3V4Z  [C_0402]  242.13 60.26 270 top
CG175  1U_0402_6.3V4Z  [C_0402]  233.12 64.62 90 top
CG176  1U_0402_6.3V4Z  [C_0402]  222.25 64.37 270 top
CG183  10U_0603_6.3V6M  [C_0603]  191.27 122.16 180 bottom
CG184  10U_0603_6.3V6M  [C_0603]  228.35 58.73 180 top
CG185  10U_0603_6.3V6M  [C_0603]  233.51 59.3 270 top
CG186  10U_0603_6.3V6M  [C_0603]  191.97 77.27 180 top
CG187  10U_0603_6.3V6M  [C_0603]  191.97 78.6 180 top
CG188  10U_0603_6.3V6M  [C_0603]  206.83 71.49 90 top
CG189  10U_0603_6.3V6M  [C_0603]  269.95 87.75 0 top
CG190  10U_0603_6.3V6M  [C_0603]  205.24 103.31 180 top
CG191  10U_0603_6.3V6M  [C_0603]  199.14 98.29 180 top
CG192  1U_0402_6.3V4Z  [C_0402]  197.68 75.16 90 top
CG193  1U_0402_6.3V4Z  [C_0402]  204.26 98.14 0 top
CG194  1U_0402_6.3V4Z  [C_0402]  250.5 82.99 0 top
CG195  1U_0402_6.3V4Z  [C_0402]  200.87 103.31 180 top
CG196  1U_0402_6.3V4Z  [C_0402]  201.74 71.43 0 top
CG197  1U_0402_6.3V4Z  [C_0402]  194.65 70.67 180 top
CG198  1U_0402_6.3V4Z  [C_0402]  193.82 78.6 180 top
CG199  1U_0402_6.3V4Z  [C_0402]  204.47 95.05 0 top
CG200  1U_0402_6.3V4Z  [C_0402]  193.95 95.69 180 top
CG201  1U_0402_6.3V4Z  [C_0402]  202.62 94.92 0 top
CG202  1U_0402_6.3V4Z  [C_0402]  190.69 81.65 0 top
CG203  1U_0402_6.3V4Z  [C_0402]  196.17 85.14 180 bottom
CG204  1U_0402_6.3V4Z  [C_0402]  200.38 93.39 90 top
CG205  1U_0402_6.3V4Z  [C_0402]  195.92 95.94 180 top
CG206  1U_0402_6.3V4Z  [C_0402]  194.69 78.6 0 top
CG207  1U_0402_6.3V4Z  [C_0402]  204.97 89.14 0 bottom
CG208  1U_0402_6.3V4Z  [C_0402]  205.23 85.21 0 bottom
CG209  1U_0402_6.3V4Z  [C_0402]  204.11 89.14 180 bottom
CG210  1U_0402_6.3V4Z  [C_0402]  204.91 71.36 0 top
CG211  1U_0402_6.3V4Z  [C_0402]  201.95 98.35 180 top
CG212  1U_0402_6.3V4Z  [C_0402]  193.95 76.76 180 top
CG213  1U_0402_6.3V4Z  [C_0402]  198.75 75.24 0 top
CG214  1U_0402_6.3V4Z  [C_0402]  192.22 75.31 270 top
CG215  1U_0402_6.3V4Z  [C_0402]  194.71 103.56 180 top
CG216  10U_0603_6.3V6M  [C_0603]  197.11 70.54 180 top
CG217  10U_0603_6.3V6M  [C_0603]  191.4 93.34 270 top
CG218  10U_0603_6.3V6M  [C_0603]  226.21 89.6 45 top
CG219  10U_0603_6.3V6M  [C_0603]  228.23 66.67 270 bottom
CG220  22U_0603_6.3V6M  [C_0603]  270.96 102.73 180 bottom
CG221  22U_0603_6.3V6M  [C_0603]  285.25 111.37 270 bottom
CG222  22U_0603_6.3V6M  [C_0603]  236.36 52.06 0 bottom
CG223  22U_0603_6.3V6M  [C_0603]  242.2 52.06 180 bottom
CG224  22U_0603_6.3V6M  [C_0603]  282.27 70.6 0 bottom
CG225  22U_0603_6.3V6M  [C_0603]  285.12 81.65 90 bottom
CG226  22U_0603_6.3V6M  [C_0603]  263.22 54.6 270 bottom
CG227  22U_0603_6.3V6M  [C_0603]  257.31 52 180 bottom
CG228  22U_0603_6.3V6M  [C_0603]  260.87 52 0 bottom
CG230  0.1U_0402_10V7K  [C_0402]  224.66 111.5 180 top
CG231  10U_0603_6.3V6M  [C_0603]  218.64 119.5 90 top
CG232  47U_0805_6.3V6M  [C_0805]  220.16 119.66 90 top
CG233  0.1U_0402_10V7K  [C_0402]  246.72 93.21 180 top
CG234  0.1U_0402_10V7K  [C_0402]  235.81 110.34 270 top
CG235  0.1U_0402_10V7K  [C_0402]  234.9 110.34 270 top
CG236  0.1U_0402_10V7K  [C_0402]  226.34 112.32 180 top
CG237  0.1U_0402_10V7K  [C_0402]  226.93 99.11 0 top
CG238  0.1U_0402_10V7K  [C_0402]  226.61 116.09 180 top
CG239  22U_0603_6.3V6M  [C_0603]  224.29 118.04 90 top
CG240  0.1U_0402_16V7K  [C_0402]  192.02 107.18 180 bottom
CG241  0.1U_0402_16V4Z~D  [C_0402]  211.91 113.1 270 bottom
CG242  470U_X_2VY_R9M  [C_X]  268.8 63.3 270 bottom
CG243  10U_0603_6.3V6M  [C_0603]  202.83 85.4 0 bottom
CG244  470U_X_2VY_R9M  [C_X]  250.71 120.01 180 top
CG245  10U_0603_6.3V6M  [C_0603]  255.09 114.8 270 top
CG246  0.1U_0201_6.3V6K  [C_0201]  215.71 161.46 0 top
CG247  22U_0603_6.3V6M  [C_0603]  227 122.55 0 top
CG256  820P_0402_25V7  [C_0402]  195.54 86.03 180 bottom
CG265  820P_0402_25V7  [C_0402]  196.4 86.92 0 bottom
CG266  22U_0603_6.3V6M  [C_0603]  228.29 57.08 270 bottom
CG267  22U_0603_6.3V6M  [C_0603]  271.98 92.7 180 top
